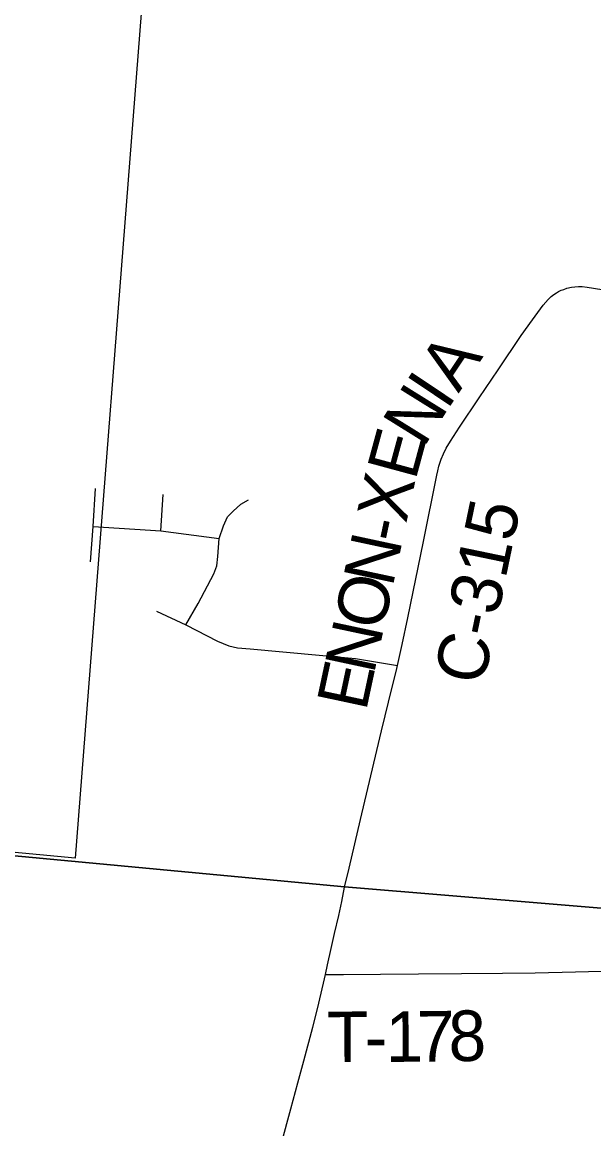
# Model space of a CAD drawing. Extents: x 0 to 1134, y 0 to 440.
# Drawn here: x 839.228 to 839.87, y 357.243 to 358.485 of the extents above; entities that cross this region are included whole.
import ezdxf

# ---------------------------------------------------------------- set-up
doc = ezdxf.new("R2010")
doc.units = 0
for name, color, linetype in [('GM_X_County_Road', 7, 'Continuous'), ('GM_X_County_Road_Text', 7, 'Continuous'), ('GM_X_Section', 7, 'Continuous'), ('GM_X_Township', 7, 'Continuous'), ('GM_X_Township_Road', 7, 'Continuous'), ('GM_X_Township_Road_Text', 7, 'Continuous'), ('GM_X_Unincorporated', 7, 'Continuous'), ('SH_Cut_Line', 7, 'Continuous')]:
    doc.layers.add(name, color=color, linetype=linetype)

msp = doc.modelspace()

# ---------------------------------------------------------------- linework, layer by layer
at = {"layer": 'GM_X_County_Road'}
for points in [[(839.5902, 357.5138), (839.5951, 357.5354), (839.608, 357.5899), (839.6197, 357.6389), (839.6317, 357.6895), (839.6437, 357.7386), (839.648, 357.7561), (839.6549, 357.7864), (839.6611, 357.8165), (839.6785, 357.902), (839.6935, 357.9766), (839.6947, 357.9817), (839.6959, 357.9866), (839.6984, 357.9946), (839.701, 358.0005), (839.7043, 358.0069), (839.7089, 358.0148), (839.719, 358.0304), (839.741, 358.0636), (839.7623, 358.0951), (839.7884, 358.1334), (839.8011, 358.1512), (839.813, 358.1675), (839.8186, 358.1738), (839.8221, 358.1772), (839.825, 358.1795), (839.828, 358.1813), (839.8303, 358.1828), (839.8333, 358.1843), (839.836, 358.1853), (839.8396, 358.1865), (839.8446, 358.1878), (839.8487, 358.1883), (839.8528, 358.1884), (839.8568, 358.1884), (839.8624, 358.1879), (839.8789, 358.1853)], [(839.5687, 357.4158), (839.5711, 357.4269), (839.5752, 357.4451), (839.5789, 357.462), (839.5835, 357.4823), (839.587, 357.498), (839.5902, 357.5138)], [(839.4704, 357.0414), (839.4712, 357.0444), (839.4776, 357.069), (839.4858, 357.0995), (839.495, 357.1335), (839.5032, 357.1653), (839.5115, 357.1978), (839.5193, 357.2264), (839.5298, 357.2651), (839.5376, 357.2944), (839.5443, 357.319), (839.5546, 357.3568), (839.5598, 357.3773), (839.5666, 357.4063), (839.5687, 357.4158)]]:
    msp.add_lwpolyline(points, dxfattribs=at)
at = {"layer": 'GM_X_Section'}
msp.add_lwpolyline([(839.3675, 358.5672), (839.2878, 357.5465), (838.2839, 357.6414), (838.3822, 358.6657)], close=True, dxfattribs=at)
at = {"layer": 'GM_X_Township'}
msp.add_lwpolyline([(840.2787, 357.2184), (840.2827, 357.263), (840.2855, 357.2907), (840.2876, 357.3141), (840.2913, 357.3543), (840.293, 357.376), (840.2953, 357.4039), (840.2966, 357.4163), (840.2971, 357.4198), (840.2979, 357.4238), (840.2989, 357.4287), (840.2997, 357.4336), (840.3015, 357.4553), (839.5899, 357.5143), (837.799, 357.6829)], dxfattribs=at)
at = {"layer": 'GM_X_Township_Road'}
msp.add_line((839.3838, 357.9141), (839.3866, 357.9548), dxfattribs=at)
for points in [[(839.305, 357.8794), (839.3078, 357.9191), (839.3106, 357.9616)], [(839.412, 357.8086), (839.4257, 357.8325), (839.4434, 357.8657), (839.4468, 357.875), (839.448, 357.8853), (839.4493, 357.9057), (839.4542, 357.9197), (839.4586, 357.9299), (839.4651, 357.9361), (839.4735, 357.9442), (839.4821, 357.9489)], [(839.3078, 357.9191), (839.3838, 357.9141), (839.4493, 357.9057)], [(839.3791, 357.8241), (839.412, 357.8086), (839.4474, 357.7903), (839.4601, 357.7851), (839.47, 357.7829), (839.4843, 357.7816), (839.6025, 357.7708), (839.6496, 357.763)], [(839.5687, 357.4158), (839.5888, 357.4158), (839.6303, 357.4161), (839.6731, 357.4165), (839.7213, 357.417), (839.7673, 357.4173), (839.8039, 357.4179), (839.8492, 357.4188), (839.8783, 357.4196), (839.9153, 357.4209), (839.9307, 357.4212), (840.0325, 357.4242), (840.0385, 357.4244)]]:
    msp.add_lwpolyline(points, dxfattribs=at)
at = {"layer": 'GM_X_Unincorporated'}
msp.add_lwpolyline([(840.2787, 357.2184), (840.2827, 357.263), (840.2855, 357.2907), (840.2876, 357.3141), (840.2913, 357.3543), (840.293, 357.376), (840.2953, 357.4039), (840.2966, 357.4163), (840.2971, 357.4198), (840.2979, 357.4238), (840.2989, 357.4287), (840.2997, 357.4336), (840.3015, 357.4553), (839.5899, 357.5143), (837.799, 357.6829)], dxfattribs=at)
at = {"layer": 'SH_Cut_Line'}
for points in [[(840.2787, 357.2184), (840.2827, 357.263), (840.2855, 357.2907), (840.2876, 357.3141), (840.2913, 357.3543), (840.293, 357.376), (840.2953, 357.4039), (840.2966, 357.4163), (840.2971, 357.4198), (840.2979, 357.4238), (840.2989, 357.4287), (840.2997, 357.4336), (840.3015, 357.4553), (839.5899, 357.5143), (837.799, 357.6829)], [(837.799, 357.6829), (839.5899, 357.5143), (840.3015, 357.4553), (840.2997, 357.4336), (840.2989, 357.4287), (840.2979, 357.4238), (840.2971, 357.4198), (840.2966, 357.4163), (840.2953, 357.4039), (840.293, 357.376), (840.2913, 357.3543), (840.2876, 357.3141), (840.2855, 357.2907), (840.2827, 357.263), (840.2787, 357.2184)]]:
    msp.add_lwpolyline(points, dxfattribs=at)

# ---------------------------------------------------------------- texts
at = {"layer": 'GM_X_County_Road_Text'}
for s, height, rotation, p in [('A', 0.0568, 56.1331, (839.718, 358.0681)), ('I', 0.0568, 56.1649, (839.705, 358.0487)), ('N', 0.0568, 58.0904, (839.6788, 358.0067)), ('E', 0.0568, 74.8281, (839.6695, 357.9697)), ('X', 0.0568, 77.9552, (839.6592, 357.9216)), ('C-315', 0.05682, 78.27, (839.7458, 357.7392)), ('-', 0.0568, 77.9284, (839.6543, 357.8988)), ('N', 0.0568, 77.9323, (839.6439, 357.8499)), ('O', 0.0568, 77.9276, (839.6334, 357.801)), ('N', 0.0568, 77.9299, (839.623, 357.7521)), ('E', 0.0568, 77.9328, (839.6141, 357.7105))]:
    msp.add_text(s, height=height, rotation=rotation, dxfattribs=at).set_placement(p)
at = {"layer": 'GM_X_Township_Road_Text'}
for s, rotation, p in [('T', 0.3171, (839.5704, 357.3174)), ('1', 0.3656, (839.6363, 357.3177)), ('7', 0.51, (839.6715, 357.318)), ('8', 1.2001, (839.7072, 357.3183)), ('-', 0.3226, (839.6129, 357.3176))]:
    msp.add_text(s, height=0.0568, rotation=rotation, dxfattribs=at).set_placement(p)

doc.saveas('drawing.dxf')
